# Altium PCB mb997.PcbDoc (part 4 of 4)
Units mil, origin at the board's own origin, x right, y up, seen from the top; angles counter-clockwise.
Board outline 2598.43 x 3818.9 mil, 2 copper layers (Top, Bottom), stack 62.402 mil thick; 205 components, 190 nets, 761 pads, 492 vias.
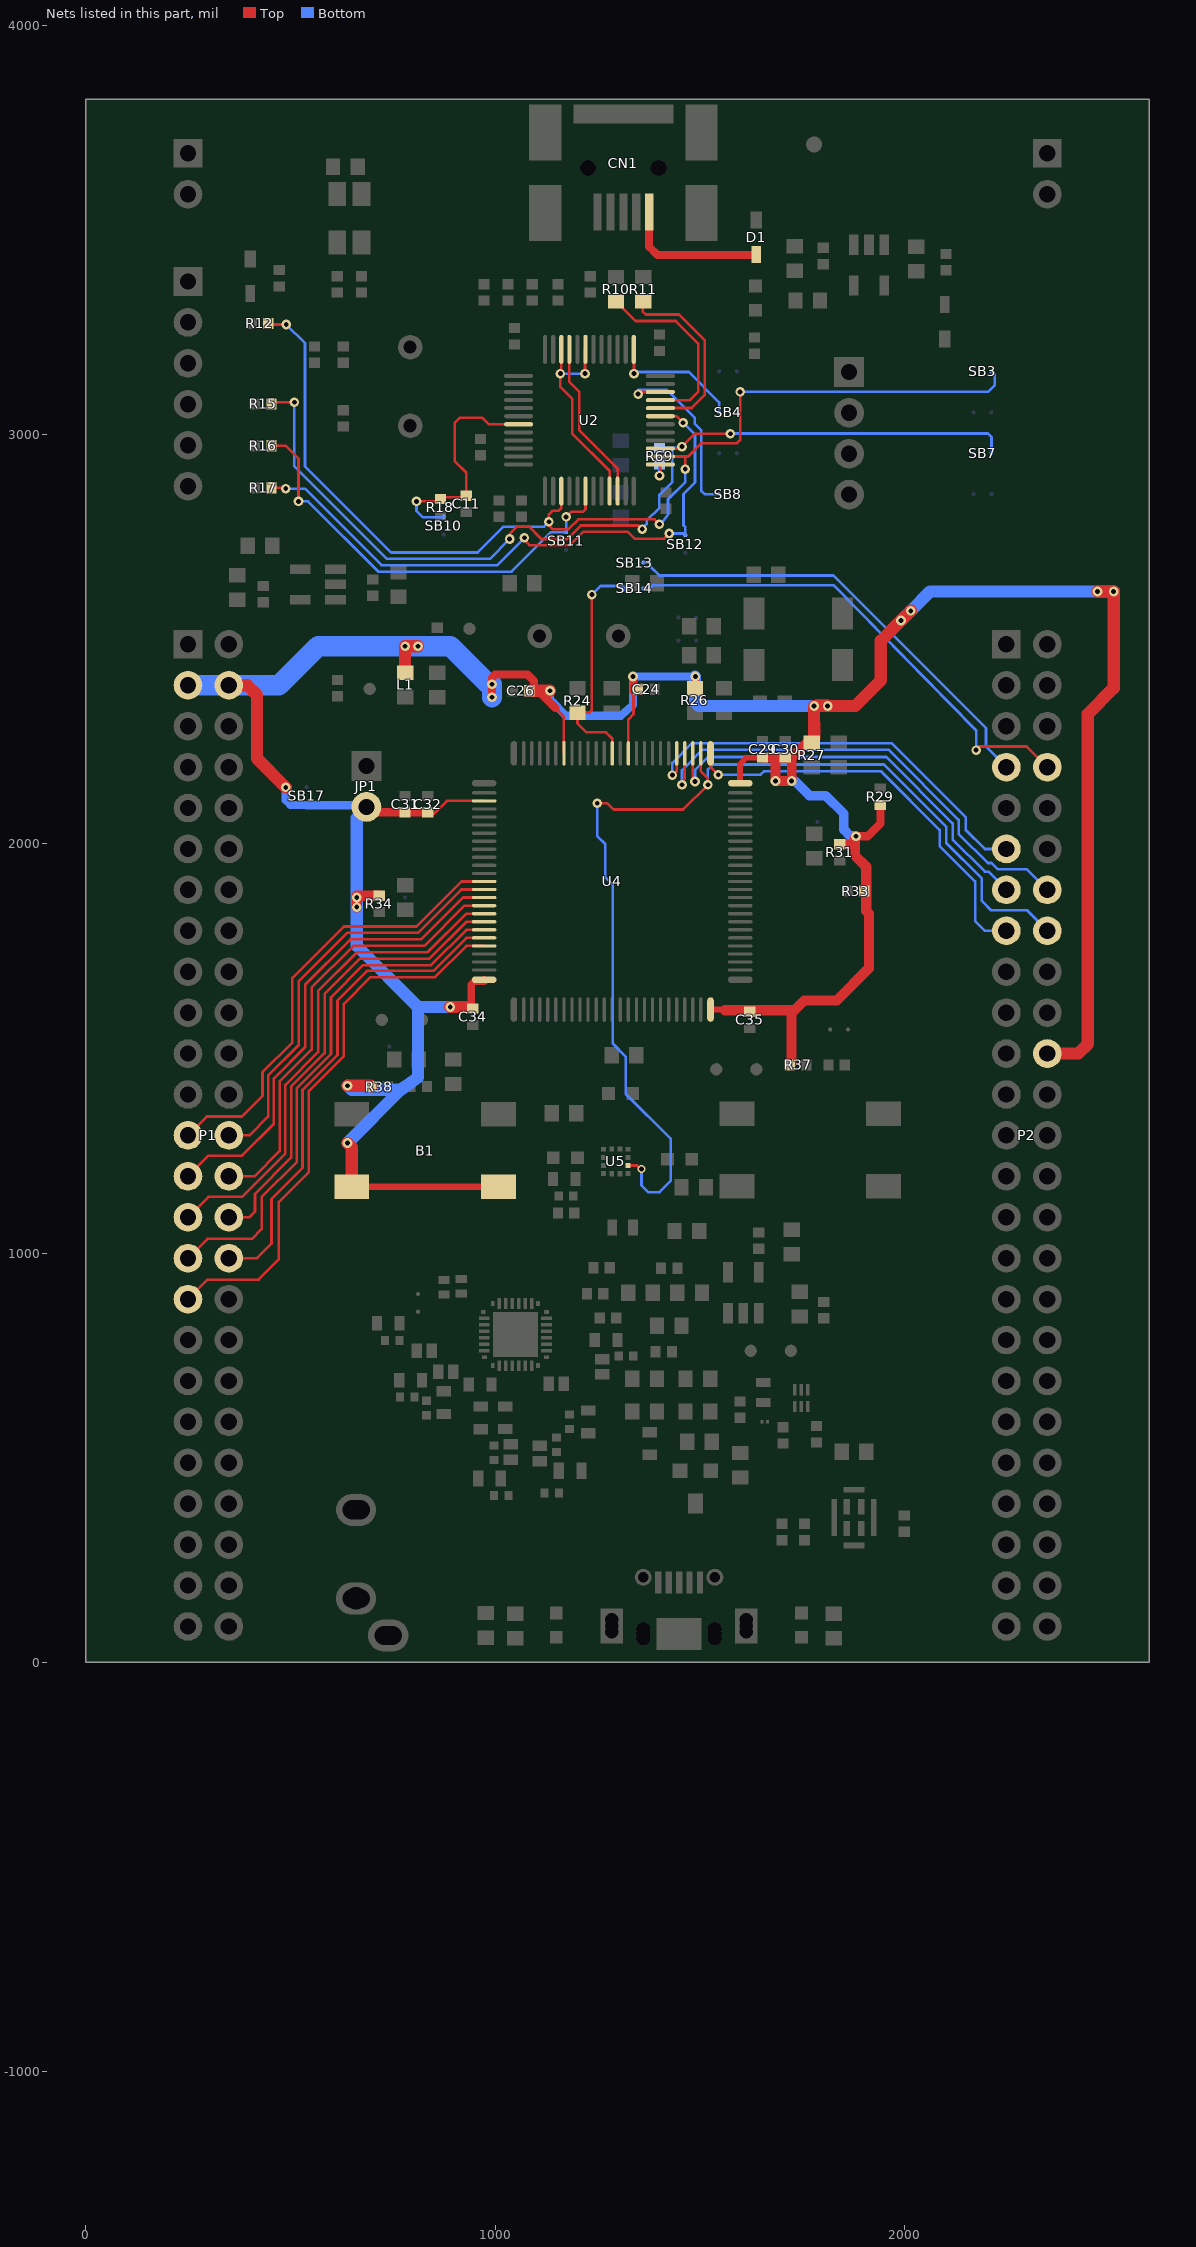
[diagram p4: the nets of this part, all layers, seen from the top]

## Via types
v1: diameter 23.62, hole 11.81, Top to Bottom, 485 vias
v2: diameter 19.68, hole 11.81, Top to Bottom, 7 vias

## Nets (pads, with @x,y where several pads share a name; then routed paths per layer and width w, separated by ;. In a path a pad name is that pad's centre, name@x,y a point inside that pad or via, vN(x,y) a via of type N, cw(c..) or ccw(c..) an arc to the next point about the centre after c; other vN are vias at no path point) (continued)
PE2: P2.15 U4.1 | length 1009.2
  Top w6.5: U4.1@1526.12,2220.94 1526.12,2186.9 1527.21,2186.9 v1(1545.21,2168.9)
  Bottom w6.5: v1(1545.21,2168.9) 1648.53,2168.9 1656.53,2176.9 1943.36,2176.9 2086.21,2034.05 2086.21,1994.7 2172.78,1908.13 2172.78,1811.01 2196.39,1787.4 P2.15@2249.21,1787.4
PE3: P2.16 U4.2 U5.2 | length 2644.3
  Top w6.5: v1(1249.21,2098.9) 1274.18,2098.9 1289.21,2083.87 1459.21,2083.87 v1(1519.57,2144.23) 1519.57,2159.97 1502.5,2177.04 U4.2@1502.5,2220.94 ; U5.2@1324.72,1214.06 1346.92,1214.06 1355.77,1205.2 v2(1357.32,1205.2)
  Bottom w6.5: v1(1249.21,2098.9) 1249.21,2018.9 1269.21,1998.9 1269.21,1917.32 1287.24,1899.29 1287.24,1511.65 1318.9,1480 1318.9,1389.21 1429.21,1278.9 1429.21,1176.69 1401.42,1148.9 1373.63,1148.9 1357.32,1165.22 v2(1357.32,1205.2) ; v1(1519.57,2144.23) 1519.57,2181.44 1532.03,2193.9 1949.97,2193.9 2101.95,2041.92 2101.95,2002.57 2188.52,1916 2188.52,1860.91 2211.83,1837.6 2299.01,1837.6 P2.16@2349.21,1787.4
PE4: P2.13 U4.3 | length 1034.1
  Top w6.5: U4.3@1482.81,2220.94 1482.81,2152.1 v1(1488.09,2152.1)
  Bottom w6.5: v1(1488.09,2152.1) 1488.09,2180.43 1519.56,2211.9 1955.58,2211.9 2117.69,2049.79 2117.69,2010.44 2196.39,1931.74 2204.88,1931.74 P2.13@2249.21,1887.4
PE5: P2.14 U4.4 | length 1190.1
  Top w6.5: v1(1456.61,2144.23) 1456.61,2153.45 1463.13,2159.97 U4.4@1463.13,2220.94
  Bottom w6.5: v1(1456.61,2144.23) 1456.61,2179.67 1506.84,2229.9 1961.19,2229.9 2132.58,2058.51 2132.58,2024.48 2203.84,1953.23 2212.56,1953.23 2227.87,1937.91 2298.7,1937.91 P2.14@2349.21,1887.4
PE6: P2.11 U4.5 | length 1050.3
  Top w6.5: v1(1433,2167.84) 1440.87,2175.71 1443.44,2175.71 U4.5@1443.44,2220.94
  Bottom w6.5: v1(1433,2167.84) 1433,2197.9 1481,2245.9 1968.8,2245.9 2149.46,2065.24 2149.46,2034.33 2196.39,1987.4 P2.11@2249.21,1987.4
PE7: P1.25 U4.38 | length 1106.9
  Top w6.5: P1.25@249.21,1287.4 295.43,1333.62 381.21,1333.62 431.21,1383.62 431.21,1441.77 504.34,1514.9 504.34,1672.03 630.26,1797.95 807.52,1797.95 917.52,1907.95 U4.38@972.97,1907.95
PE8: P1.26 U4.39 | length 1022.5
  Top w6.5: P1.26@349.21,1287.4 399.21,1287.4 445.21,1333.4 445.21,1434.03 520.08,1508.9 520.08,1664.16 638.13,1782.21 811.27,1782.21 917.33,1888.26 U4.39@972.97,1888.26
PE9: P1.27 U4.40 | length 1160.4
  Top w6.5: P1.27@249.21,1187.4 299.72,1237.91 381.21,1237.91 459.21,1315.91 459.21,1426.29 535.82,1502.9 535.82,1656.29 646,1766.47 819.14,1766.47 921.25,1868.58 U4.40@972.97,1868.58
PE10: P1.28 U4.41 | length 1085.6
  Top w6.5: P1.28@349.21,1187.4 411.21,1187.4 473.21,1249.4 473.21,1418.55 551.56,1496.9 551.56,1648.42 653.87,1750.73 827.01,1750.73 925.18,1848.89 U4.41@972.97,1848.89
PE11: P1.29 U4.42 | length 1216.8
  Top w6.5: P1.29@249.21,1087.4 299.2,1137.39 381.21,1137.39 487.21,1243.39 487.21,1410.81 567.3,1490.9 567.3,1640.55 661.74,1734.99 835.1,1734.99 929.32,1829.21 U4.42@972.97,1829.21
PE12: P1.30 U4.43 | length 1134.6
  Top w6.5: P1.30@349.21,1087.4 399.21,1087.4 413.02,1101.21 413.02,1144.7 501.21,1232.9 501.21,1406.9 583.04,1488.73 583.04,1632.68 669.61,1719.25 839.05,1719.25 929.32,1809.52 U4.43@972.97,1809.52
PE13: P1.31 U4.44 | length 1288.5
  Top w6.5: P1.31@249.21,987.4 296.37,1034.56 405.21,1034.56 429.21,1058.56 429.21,1136.9 515.21,1222.9 515.21,1402.9 598.78,1486.47 598.78,1624.81 677.48,1703.51 842.99,1703.51 929.32,1789.84 U4.44@972.97,1789.84
PE14: P1.32 U4.45 | length 1201.5
  Top w6.5: P1.32@349.21,987.4 417.77,987.4 453.24,1022.87 453.24,1131.9 529.21,1207.87 529.21,1398.9 614.52,1484.21 614.52,1616.94 687.2,1689.61 848.78,1689.61 929.32,1770.15 U4.45@972.97,1770.15
PE15: P1.33 U4.46 | length 1353.7
  Top w6.5: P1.33@249.21,887.4 296.89,935.08 421.39,935.08 471.21,984.9 471.21,1124.9 544.71,1198.4 544.71,1396.4 630.26,1481.95 630.26,1609.07 695.27,1674.08 853.19,1674.08 929.58,1750.47 U4.46@972.97,1750.47
PH0: P2.7 SB13.2 | length 1126.1
  Bottom w6.5: SB13.2@1362.18,2687.26 1378.81,2687.26 1378.81,2678.18 1401.21,2655.78 1826.5,2655.78 2199.21,2283.07 2199.21,2237.4 P2.7@2249.21,2187.4
PH1: P2.8 SB14.2 | length 1214
  Top w6.5: v1(2175.21,2228.9) 2181.21,2234.9 2181.21,2237.91 2298.7,2237.91 P2.8@2349.21,2187.4
  Bottom w6.5: SB14.2@1362.18,2624.3 1377.97,2624.3 1385.84,2632.17 1826.5,2632.17 2175.21,2277.46 v1(2175.21,2228.9)
PH1-OSC_OUT: R24.2 SB14.1 U4.13 | length 588.8
  Top w6.5: v1(1236.21,2608.9) 1236.21,2326.9 1229.21,2319.9 R24.2@1201.21,2319.9 1201.21,2293.9 1222.84,2272.27 1270.59,2272.27 1285.96,2256.9 U4.13@1285.96,2220.94
  Bottom w6.5: v1(1236.21,2608.9) 1257.21,2629.9 1313.21,2629.9 1313.21,2618.63 ; 1311.84,2617.27 1313.21,2618.63 ; SB14.1@1318.88,2624.3 1313.21,2618.63
STM_JTCK: SB4.2 U2.37 | length 324.4
  Top w6.5: U2.37@1338.61,3208.23 1338.61,3198.9 1339.21,3198.29 v1(1339.21,3148.9)
  Bottom w6.5: v1(1339.21,3148.9) 1343.21,3152.89 1473.21,3152.89 1547.2,3078.9 SB4.2@1547.2,3054.37
STM_JTMS: SB8.2 U2.34 | length 468.1
  Top w6.5: v1(1349.21,3098.9) 1349.21,3103.59 1348.91,3103.9 U2.34@1403.57,3103.9
  Bottom w6.5: v1(1349.21,3098.9) 1349.21,3108.9 1419.21,3108.9 1487.96,3040.15 1487.96,3026.02 1503.83,3010.15 1503.83,2862.24 1511.7,2854.37 SB8.2@1547.2,2854.37
STM_RST: C11.2 R18.1 SB10.2 U2.7 | length 580.6
  Top w6.5: v1(807.81,2836.7) 856.53,2836.7 R18.1@866.14,2842.83 870.03,2846.73 925.15,2846.73 C11.2@929.13,2850.71 929.21,2906.9 901.41,2934.7 901.41,3029.24 913.58,3041.41 968.16,3041.41 984.41,3025.16 U2.7@1057.11,3025.16
  Bottom w6.5: v1(807.81,2836.7) 807.81,2813.3 823.41,2797.7 870.21,2797.7 871.73,2799.21 SB10.2@874.02,2799.21
SWIM: U2.22 U2.45 | length 395.4
  Top w6.5: U2.45@1181.13,3208.23 1181.13,3128.92 1205.23,3104.82 1205.23,3011.33 1299.24,2917.32 U2.22@1299.24,2861.77
SWIM_IN: U2.21 U2.43 U2.46 | length 517.1
  Top w6.5: U2.46@1161.44,3208.23 1161.44,3153.54 1159.21,3151.32 v1(1159.21,3148.9) 1159.21,3116.4 1188.01,3087.6 1188.01,3003.14 1279.55,2911.6 U2.21@1279.55,2861.77 ; v1(1219.21,3148.9) 1219.21,3206.94 U2.43@1220.5,3208.23
  Bottom w6.5: v1(1159.21,3148.9) v1(1219.21,3148.9)
T_JTCK: R12.2 SB3.1 U2.15 U2.26 | length 2706.2
  Top w6.5: R12.2@445.2,3271.65 447.95,3268.9 v1(489.21,3268.9) ; U2.15@1161.44,2861.77 1161.44,2821.1 1154.17,2813.82 1140.14,2813.82 1131.21,2804.9 v1(1131.21,2786.9) 1131.21,2777.9 1140.21,2768.9 1179.21,2768.9 1203.21,2792.9 1389.21,2792.9 v1(1401.21,2780.9) ; U2.26@1403.57,2946.42 1464.48,2946.42 ; v1(1464.48,2915.49) 1464.48,2946.42 ; v1(1598.43,3104.37) 1598.43,2986.4 1590.93,2978.9 1504.19,2978.9 1471.71,2946.42 1464.48,2946.42
  Bottom w6.5: v1(489.21,3268.9) 535.31,3223.3 535.31,2922 745.41,2711.9 957.21,2711.9 1020.21,2774.9 1119.21,2774.9 v1(1131.21,2786.9) ; v1(1401.21,2780.9) 1404.38,2780.9 1422.38,2804.9 1422.38,2841.91 1464.48,2884.01 v1(1464.48,2915.49) ; v1(1598.43,3104.37) 2204.72,3104.37 2220.47,3120.12 2220.47,3146.46 SB3.1@2212.56,3154.37
T_JTMS: R15.2 R69.2 SB7.1 U2.27 | length 2380.6
  Top w6.5: R15.2@453.07,3074.8 457.17,3078.9 v1(509.21,3078.9) ; v1(1035.21,2744.9) 1035.21,2756.9 1053.21,2774.9 1082.49,2774.9 1112.49,2744.9 1176.21,2744.9 1209.21,2777.9 1350.21,2777.9 v1(1359.21,2768.9) ; U2.27@1403.57,2966.1 1448.74,2966.1 v1(1456.61,2970.58) 1488.09,3002.06 v1(1574.66,3002.06)
  Bottom w6.5: v1(509.21,3078.9) 509.21,2922.5 735.41,2696.3 987.21,2696.3 1035.21,2744.3 v1(1035.21,2744.9) ; v1(1359.21,2768.9) 1359.21,2770.07 1370.04,2780.9 1370.04,2789.57 1401.13,2820.66 1401.13,2852.14 1433,2884.01 1433,2966.97 ; R69.2@1401.52,2966.97 1433,2966.97 ; v1(1456.61,2970.58) 1456.61,2968.77 1454.81,2966.97 1433,2966.97 ; v1(1574.66,3002.06) 1575.09,3002.48 2204.26,3002.48 2212.56,2994.19 SB7.1@2212.56,2954.37
T_NRST: R16.2 SB11.1 U2.18 | length 1085.7
  Top w6.5: R16.2@453.07,2972.44 488.19,2972.44 519.21,2941.42 v1(519.21,2836.7) ; v1(1173.21,2798.9) 1185.57,2811.26 1214.85,2811.26 1220.5,2816.9 U2.18@1220.5,2861.77
  Bottom w6.5: v1(519.21,2836.7) 542.61,2836.7 714.21,2665.1 1040.21,2665.1 1136.7,2761.58 SB11.1@1173.21,2761.58 v1(1173.21,2798.9)
T_SWDIO_IN: R69.1 U2.25 | length 56.2
  Top w6.5: v1(1401.52,2899.75) 1403.57,2899.75 U2.25@1403.57,2926.73
  Bottom w6.5: v1(1401.52,2899.75) R69.1@1401.52,2926.97
T_SWO: R17.2 SB12.1 U2.31 | length 1519.3
  Top w6.5: R17.2@453.07,2870.08 485.83,2870.08 v1(488.01,2867.9) ; v1(1071.21,2747.9) 1071.21,2741.9 1083.21,2729.9 1182.21,2729.9 1215.21,2762.9 1323.21,2762.9 1340.58,2745.53 1412.58,2745.53 v1(1425.13,2758.09) ; U2.31@1403.57,3044.84 1443.27,3044.84 v1(1459.21,3028.9)
  Bottom w6.5: v1(488.01,2867.9) 534.81,2867.9 722.01,2680.7 1005.21,2680.7 1071.21,2746.7 v1(1071.21,2747.9) ; v1(1425.13,2758.09) 1460.56,2758.09 SB12.1@1464.48,2754.16 1464.48,2773.83 1460.23,2778.08 1460.23,2854.85 1488.09,2882.71 1488.09,3000.02 v1(1459.21,3028.9)
U5V: CN1.1 D1.1 | length 354.8
  Top w19.68: CN1.1@1376.23,3543.35 1376.23,3458.9 1396.23,3438.9 1636.46,3438.9 D1.1@1637.76,3440.2
USB_DM: R11.2 U2.32 | length 462.5
  Top w6.5: R11.2@1362.17,3325.16 1360.21,3325.16 1360.21,3301.12 1368.08,3293.25 1449.12,3293.25 1511.7,3230.66 1511.7,3096.5 1480.22,3065.02 1403.57,3065.02 U2.32@1403.57,3064.53
USB_DP: R10.2 U2.33 | length 462.1
  Top w6.5: R10.2@1295.24,3325.16 1342.89,3277.51 1440.87,3277.51 1495.96,3222.42 1495.96,3104.37 1475.81,3084.21 U2.33@1403.57,3084.21
VDD: B1.3 B1.4 C24.1 C26.2 C29.2 C30.2 C31.2 C32.2 C34.2 C35.1 JP1.2 L1.1 P1.3 P1.4 P2.22 R26.1 R27.2 R29.1 R31.2 R33.1 R34.1 R37.2 R38.2 SB17.2 U4.11 U4.19 U4.28 U4.50 U4.75 U4.100 | length 9415.6
  Top w6.5: C32.2@834.88,2077.01 838.49,2073.4 850.7,2073.4 882.1,2104.8 U4.28@972.97,2104.8 ; 1102.36,2374.02 1104.86,2374.02 ; 1146.81,2332.06 1167.85,2311.02 U4.19@1167.85,2220.94 ; U4.11@1325.33,2220.94 1325.33,2303.9 1338.11,2316.68 C24.1@1338.11,2372.4 ; 1685.04,2208.66 1685.04,2210.16 ; 1879.42,1971.09 1880.51,1970 ; R33.1@1901.59,1884.52 1901.59,1918.01 1906.43,1922.85
  Top w13.78: U4.100@1598.96,2148.11 1598.96,2151.41 1598.27,2152.1 1598.27,2194.75 1614.01,2210.49 1636.76,2210.49 C29.2@1653.36,2210.8
  Top w15: U4.75@1526.12,1594.96 1559.75,1594.96 1561.71,1592.99
  Top w15.75: B1.3@649.62,1161.92 B1.4@1007.89,1161.92
  Top w18: C34.2@937.19,1601.2 940.8,1597.59 C34.2@941.87,1596.52 ; C34.2@945.06,1597.59 C34.2@941.87,1596.52 ; U4.50@972.97,1667.79 972.97,1664.16 949.74,1664.16 941.87,1656.29 C34.2@941.87,1596.52
  Top w19.68: v1(992.13,2358.27) v1(992.13,2389.76) 992.13,2405.51 1000,2413.39 1078.74,2413.39 1094.49,2397.64 C26.2@1094.49,2374.02 ; v1(1336.71,2408.9) 1337.37,2408.16 1338.11,2407.42 1338.11,2372.4 1339.05,2371.46 1340.53,2372.4 C24.1@1349.21,2377.9 ; R26.1@1488.19,2380.39 1488.19,2407.87 v1(1489.21,2408.9)
  Top w20: JP1.2@693.22,2094.23 710.44,2077.01 C31.2@779.79,2077.01 C32.2@834.88,2077.01 ; 1104.86,2374.02 1119.36,2359.52 1146.81,2332.06 ; v1(1881.59,2018.31) 1909.73,2018.31 1941.21,2049.79 R29.1@1941.21,2094.9
  Top w23.62: C29.2@1653.36,2210.8 1685.04,2210.16 C30.2@1708.45,2210.8 1724.41,2210.16 ; v1(1685.04,2153.54) v1(1724.41,2153.54) 1724.41,2210.16 ; R27.2@1773.21,2246.9 1773.14,2246.26 1760.51,2246.26 1724.41,2210.16 ; R31.2@1842.24,1998.96 1875.16,1998.96 v1@1879.42,2018.31 ; 1879.42,1971.09 v1@1879.42,2018.31 ; v1(1881.59,2018.31) v1@1879.42,2018.31
  Top w25: v1(661.74,1845.17) v1(661.74,1868.78) 661.74,1873.04 R34.1@716.83,1873.04 ; 1561.71,1592.99 1637.8,1592.99 ; C35.1@1621.88,1589.72 1637.8,1592.99 ; v1(1685.04,2153.54) 1685.04,2208.66 ; R37.2@1719.93,1459.54 1724.05,1463.65 1724.05,1483.16 1723.95,1522.5 1723.95,1585.46 ; 1880.51,1970 1906.43,1944.07 1906.43,1922.85 1906.43,1836.07 1913.07,1829.43 1913.07,1695.64 1834.37,1616.94 1755.43,1616.94 1723.95,1585.46 ; 1637.8,1592.99 1723.95,1592.99 1723.95,1585.46
  Top w30: P1.4@349.21,2387.4 394.16,2387.4 417.77,2363.79 417.77,2208.21 v1(488.19,2137.8) ; v1(639.21,1268.9) 649.62,1258.49 B1.3@649.62,1161.92 ; v1(639.21,1408.9) 695.21,1408.9 R38.2@697.21,1406.9 ; L1.1@779.79,2418.2 v1(779.79,2482.64) v1(811.27,2482.64) ; v1(889.97,1601.2) C34.2@937.19,1601.2 ; C26.2@1082.99,2374.02 1094.49,2374.02 1102.36,2374.02 ; 1104.86,2374.02 v1(1133.86,2374.02) ; R27.2@1773.21,2246.9 1773.67,2253.12 1779.53,2258.98 v1(1779.21,2336.9) 1785.2,2336.66 1879.59,2336.66 1942.04,2399.11 1942.04,2495.86 v1(1991.77,2545.6) v1(2015.38,2569.21) ; P2.22@2349.21,1487.4 2424.62,1487.4 2448.23,1511.01 2448.23,2317.37 2511.19,2380.33 v1(2511.19,2616.43) v1(2471.84,2616.43)
  Bottom w6.5: v1@1133.86,2372.46 v1(1133.86,2374.02)
  Bottom w19.68: v1(488.19,2137.8) 488.19,2106.3 499.21,2095.28 SB17.2@539.21,2095.28 540.26,2094.23 JP1.2@693.22,2094.23 ; v1@1133.86,2372.46 1133.86,2352.33 1173.29,2312.9 1307.08,2312.9 1334.1,2336.51 ; v1(1336.71,2408.9) 1488.09,2408.9 v1(1489.21,2408.9)
  Bottom w20: 1334.1,2336.51 1336.71,2339.13 v1(1336.71,2408.9)
  Bottom w23.62: 1708.66,2153.54 v1(1724.41,2153.54) 1732.06,2153.54 1768.08,2117.53 1807.67,2117.53 1851.8,2073.4 1851.8,2034.64 1867.54,2018.9 1878.5,2018.9 v1(1881.59,2018.31)
  Bottom w25: v1(1685.04,2153.54) 1708.66,2153.54
  Bottom w30: v1(639.21,1268.9) 769.21,1398.9 ; v1(639.21,1408.9) 649.21,1398.9 769.21,1398.9 ; JP1.2@693.22,2094.23 661.74,2062.75 v1(661.74,1868.78) v1(661.74,1845.17) 661.74,1750.73 811.27,1601.2 ; v1(889.97,1601.2) 811.27,1601.2 ; v1@1488.09,2408.9 1488.09,2346.02 1497.21,2336.9 1503.21,2336.96 v1@1779.52,2336.96 ; v1(1779.21,2336.9) v1@1779.52,2336.96 ; v1(1812.21,2336.9) 1812.15,2336.96 1811.06,2338.05 v1@1784.99,2338.05 ; v1(1991.77,2545.6) v1(2015.38,2569.21) 2062.6,2616.43 v1(2471.84,2616.43) v1(2511.19,2616.43) ; 769.21,1398.9 811.27,1428.9 811.27,1601.2 ; v1@1779.52,2336.96 1783.9,2336.96 v1@1784.99,2338.05 ; v1@1779.52,2336.96 v1@1784.99,2338.05
  Bottom w50: P1.3@249.21,2387.4 P1.4@349.21,2387.4 471.69,2387.4 566.93,2482.64 v1(779.79,2482.64) v1(811.27,2482.64) 890.76,2482.64 983.63,2389.76 v1(992.13,2389.76) v1(992.13,2358.27)
pads on no net: CN1.6 CN1.7 CN1.8 CN1.9 CN1.10 CN1.11 CN1.12 CN5.0/3 CN5.0/4 CN5.0/5 CN5.6 CN5.6/2 CN5.6/3 CN5.6/4 CN5.6/5 CN5.6/6 P1.48 U2.4 U2.11 U2.12 U2.13 U2.14 U2.16 U2.17 U2.19 U2.28 U2.38 U2.39 U2.40 U2.41 U2.42 U5.5 U7.16 U7.17 U7.18 U7.20 U7.31 X3.2 X3.3

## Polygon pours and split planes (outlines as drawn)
GND on Top "Top-GND" (hatched 45Degree grid 11.81 track 13.78, remove dead copper, pour order 2): 6.89,3785.24 2591.54,3785.24 2591.54,6.89 6.89,6.89
GND on Bottom "Bottom-GND" (hatched 45Degree grid 11.81 track 13.78, remove dead copper, pour order 0): 6.89,3793.11 2591.54,3793.11 2591.54,6.89 6.89,6.89

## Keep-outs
Top:
  region: 1516,118 1577,118 1577,77 1516,77
Bottom:
  circle w7.87: c1779.41,3709.21 r29.33
Keep-Out Layer:
  the board outline again, w10

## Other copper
Top:
  pour cut-out: 1799.96,802.33 1677.96,802.33 1677.96,709.33 1799.96,709.33
  pour cut-out: 1706.76,1495.68 1584.76,1495.68 1584.76,1402.68 1706.76,1402.68
  pour cut-out: 791.47,1616.5 669.47,1616.5 669.47,1523.5 791.47,1523.5
  pour cut-out: 983.79,2456.83 983.79,2578.83 890.79,2578.83 890.79,2456.83
  pour cut-out: 740,2408 740,2530 647,2530 647,2408
  text "TOP Layer" at -33,-1009.78 h118.11
  text ".GTL" at 1643,-1016.77 h118.11
Bottom:
  pour cut-out: 1747.93,2033.42 1824.93,2033.42 1824.93,2103.42 1747.93,2103.42
  pour cut-out: 741,1888 818,1888 818,1958 741,1958
  text "Bottom Layer" at 2736.5,-997.78 h118.11
  text ".GBL" at 1054,-1010.77 h118.11

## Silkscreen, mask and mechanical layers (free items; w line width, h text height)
Silkscreen Top:
  circle w12: c2165.35,2555.12 r15.75
  circle w12: c165.35,3374.02 r17.61
  circle w12: c2165.35,2555.12 r7.87
  circle w12: c157.48,2547.24 r7.87
  circle w12: c1850.39,3232.28 r7.87
  circle w12: c2165.35,2555.12 r17.61
  circle w12: c1850.39,3232.28 r15.75
  circle w12: c165.35,3374.02 r15.75
  circle w12: c1850.39,3232.28 r7.87
  circle w12: c157.48,2547.24 r15.75
  circle w12: c165.35,3374.02 r7.87
  circle w12: c157.48,2547.24 r7.87
  circle w12: c2165.35,2555.12 r7.87
  circle w12: c157.48,2547.24 r17.61
  circle w12: c1850.39,3232.28 r17.61
  circle w12: c165.35,3374.02 r7.87
  lines w5: 442.52,3435.72 462.97,3435.72 ; 678.87,2305.89 707,2305.89 ; 692.94,2295.66 692.94,2316.11 ; 883.35,1569.44 903.81,1569.44 ; 893.58,1555.37 893.58,1583.5 ; 922.66,2354.72 950.78,2354.72 ; 936.72,2344.49 936.72,2364.94 ; 1143.7,605.92 1171.82,605.92 ; 1157.76,595.69 1157.76,616.14 ; 1457.32,1449.18 1477.77,1449.18 ; 1467.55,1435.12 1467.55,1463.24 ; 1529.34,727.91 1549.79,727.91 ; 1539.57,713.85 1539.57,741.97 ; 1678.7,3531.03 1699.15,3531.03 ; 2036.98,3226.53 2057.44,3226.53
  lines w6: 330.71,2704.72 342.52,2692.91 417.32,2692.91 431.1,2679.13 431.1,2673.23 ; 803.15,2578.74 858.27,2578.74 874.02,2594.49 ; 897.84,3419.17 897.84,3379.82 937.19,3379.82 ; 968.67,1388.71 976.54,1380.84 1047.37,1380.84 1070.98,1404.45 ; 1430.55,502.5 1430.55,612.5 ; 1440.87,2466.9 1433,2474.77 1433,2561.34 1472.35,2600.69 ; 1629.75,704.86 1635.74,710.84 1764.13,710.84
  lines w10: 0,0 2598.42,0 2598.42,3818.9 0,3818.9 0,0
  lines w19.68: 1754.92,2833.66 1792.42,2833.66 1792.42,2968.66 1754.92,2968.66 1754.92,2833.66 ; 1754.92,3059.41 1792.42,3059.41 1792.42,3194.41 1754.92,3194.41 1754.92,3059.41
  lines w39.37: 1942.42,2845.1 1964.92,2845.1 1964.92,2965.1 1942.42,2965.1 1942.42,2845.1 ; 1942.42,3070.47 1964.92,3070.47 1964.92,3190.47 1942.42,3190.47 1942.42,3070.47
  text "STM32F407G-DISC1" at 340,3706 h110.24
  text "COM" at 736.18,3496.89 h55
  text "MB997G" at 2199.21,3260.36 h118.11
  text "PWR" at 1549.21,3248.9 h78.74 r90
  text "SWD" at 165.35,3082.68 h118.11 r90
  text "ST-LINK" at 1719.21,2878.9 h98.43 r90
  text "DISCOVERY" at 2061,2835 h98.43 r90
  text "J" at 2145.63,2835.31 h600
  text "www.st.com/stm32f4-discovery" at 670.17,2703.33 h118.11
  text "GND" at 39.37,2468.9 h78.74
  text "GND" at 413.39,2468.9 h78.74
  text "GND" at 2047.24,2468.9 h78.74
  text "GND" at 2421.26,2468.9 h78.74
  text "VDD" at 39.37,2368.9 h78.74
  text "VDD" at 413.39,2368.9 h78.74
  text "5V" at 2047.24,2368.9 h78.74
  text "5V" at 2421.26,2368.9 h78.74
  text "GND" at 39.37,2268.9 h78.74
  text "NRST" at 413.39,2268.9 h78.74
  text "3V" at 2047.24,2268.9 h78.74
  text "3V" at 2421.26,2268.9 h78.74
  text "PC1" at 39.37,2168.9 h78.74
  text "PC0" at 413.39,2168.9 h78.74
  text "PH0" at 2047.24,2168.9 h78.74
  text "PH1" at 2421.26,2168.9 h78.74
  text "PC3" at 39.37,2068.9 h78.74
  text "PC2" at 413.39,2068.9 h78.74
  text "PC14" at 2047.24,2068.9 h78.74
  text "PC15" at 2421.26,2068.9 h78.74
  text "Idd" at 637.8,1972.44 h78.74
  text "PA1" at 39.37,1968.9 h78.74
  text "PA0" at 413.39,1968.9 h78.74
  text "PE6" at 2047.24,1968.9 h78.74
  text "PC13" at 2421.26,1968.9 h78.74
  text "PA3" at 39.37,1868.9 h78.74
  text "PA2" at 413.39,1868.9 h78.74
  text "PE4" at 2047.24,1868.9 h78.74
  text "PE5" at 2421.26,1868.9 h78.74
  text "PA5" at 39.37,1768.9 h78.74
  text "PA4" at 413.39,1768.9 h78.74
  text "PE2" at 2047.24,1768.9 h78.74
  text "PE3" at 2421.26,1768.9 h78.74
  text "PA7" at 39.37,1668.9 h78.74
  text "PA6" at 413.39,1668.9 h78.74
  text "PE0" at 2047.24,1668.9 h78.74
  text "PE1" at 2421.26,1668.9 h78.74
  text "PC5" at 39.37,1568.9 h78.74
  text "PC4" at 413.39,1568.9 h78.74
  text "PB8" at 2047.24,1568.9 h78.74
  text "PB9" at 2421.26,1568.9 h78.74
  text "PB1" at 39.37,1468.9 h78.74
  text "PB0" at 413.39,1468.9 h78.74
  text "BOOT0" at 2007.87,1468.9 h78.74
  text "VDD" at 2421.26,1468.9 h78.74
  text "GND" at 39.37,1368.9 h78.74
  text "PB2" at 413.39,1368.9 h78.74
  text "PB6" at 2047.24,1368.9 h78.74
  text "PB7" at 2421.26,1368.9 h78.74
  text "PE7" at 39.37,1268.9 h78.74
  text "PE8" at 413.39,1268.9 h78.74
  text "PB4" at 2047.24,1268.9 h78.74
  text "PB5" at 2421.26,1268.9 h78.74
  text "PE9" at 39.37,1168.9 h78.74
  text "PE10" at 413.39,1168.9 h78.74
  text "PD7" at 2047.24,1168.9 h78.74
  text "PB3" at 2421.26,1168.9 h78.74
  text "Reset" at 1793.83,1070.56 h78.74
  text "PE11" at 39.37,1068.9 h78.74
  text "PE12" at 413.39,1068.9 h78.74
  text "User" at 746.21,1068.9 h78.74
  text "PD5" at 2047.24,1068.9 h78.74
  text "PD6" at 2421.26,1068.9 h78.74
  text "PE13" at 39.37,968.9 h78.74
  text "PE14" at 413.39,968.9 h78.74
  text "PD3" at 2047.24,968.9 h78.74
  text "PD4" at 2421.26,968.9 h78.74
  text "PE15" at 39.37,868.9 h78.74
  text "PB10" at 413.39,868.9 h78.74
  text "PD1" at 2047.24,868.9 h78.74
  text "PD2" at 2421.26,868.9 h78.74
  text "PB12" at 413.39,768.9 h78.74
  text "PC12" at 2047.24,768.9 h78.74
  text "PD0" at 2421.26,768.9 h78.74
  text "PB11" at 39.37,767.72 h78.74
  text "PB14" at 413.39,668.9 h78.74
  text "PC10" at 2047.24,668.9 h78.74
  text "PC11" at 2421.26,668.9 h78.74
  text "PB13" at 39.37,665.35 h78.74
  text "PB15" at 39.37,568.9 h78.74
  text "PD8" at 413.39,568.9 h78.74
  text "PA14" at 2047.24,568.9 h78.74
  text "PA15" at 2421.26,568.9 h78.74
  text "PD9" at 39.37,468.9 h78.74
  text "PD10" at 413.39,468.9 h78.74
  text "PA10" at 2047.24,468.9 h78.74
  text "PA13" at 2421.26,468.9 h78.74
  text "PD12" at 413.39,368.9 h78.74
  text "PA8" at 2047.24,368.9 h78.74
  text "PA9" at 2421.26,368.9 h78.74
  text "PD11" at 39.37,366.14 h78.74
  text "PD14" at 413.39,268.9 h78.74
  text "PC8" at 2047.24,268.9 h78.74
  text "PC9" at 2421.26,268.9 h78.74
  text "PD13" at 39.37,263.78 h78.74
  text "PD15" at 39.37,168.9 h78.74
  text "NC" at 413.39,168.9 h78.74
  text "PC6" at 2047.24,168.9 h78.74
  text "PC7" at 2421.26,168.9 h78.74
  text "GND" at 39.37,68.9 h78.74
  text "GND" at 413.39,68.9 h78.74
  text "GND" at 2047.24,68.9 h78.74
  text "GND" at 2421.26,68.9 h78.74
  text "TOP Silksceen Overlay" at -33,-1009.78 h118.11
  text ".GTO" at 1613,-1018.46 h118.11
Silkscreen Bottom:
  lines w7.87: 1507.83,2772.99 1507.83,3192.99 1635.33,3192.99 1635.33,2772.99 1507.83,2772.99 ; 2129.88,2769.06 2129.88,3189.06 2257.38,3189.06 2257.38,2769.06 2129.88,2769.06
  text "DEFAULT" at 2049,2846 h98.43 r270
  text "RESERVED" at 1669,2835 h98.43 r270
  text "I" at 1461,671.9 h500
  text "C" at 1876.71,654.88 h400
  text "E" at 2142.75,642.38 h400
  text "G" at 791.51,636.43 h400
  text "F" at 1080.82,636.32 h400
  text "H" at 1565.03,313.46 h500
  text "Bottom silkscreen Overlay" at 2784,-1008.78 h118.11
  text ".GBO" at 1080,-1013.77 h118.11
Solder Mask Top:
  text "TOP Solder Mask" at -26,-1011.77 h118.11
  text ".GTS" at 1633,-1016.77 h118.11
Solder Mask Bottom:
  text "Bottom Solder Mask" at 2749.91,-998.77 h118.11
  text ".GBS" at 1042,-1006.77 h118.11
Layer_3:
  lines w6: 992.12,1223.9 1559.05,1223.9 ; 1319.21,924.69 1319.21,1491.62 ; 1155.21,1059.06 1155.21,1389.76 1482.21,1389.76 1482.21,1059.06 1155.21,1059.06
Board:
  the board outline again, w10
Drill Drawing:
  circle w10: c3326.36,446.88 r27.18
  circle w10: c3326.36,446.88 r45.31
  circle w10: c3326.36,243 r45.31
  lines w1: 0,1909.45 0.03,1909.45 ; 249.21,87.4 249.24,87.4 ; 249.21,2487.4 249.24,2487.4 ; 249.21,3587.4 249.24,3587.4 ; 249.21,3687.4 249.24,3687.4 ; 349.21,87.4 349.24,87.4 ; 1299.21,0 1299.24,0 ; 1299.21,3818.9 1299.24,3818.9 ; 2249.21,87.4 2249.24,87.4 ; 2349.21,87.4 2349.24,87.4 ; 2349.21,3687.4 2349.24,3687.4 ; 2598.43,1909.45 2598.45,1909.45
  lines w10: 3281.05,-187.4 3303.7,-187.4 3326.36,-210.06 3349.01,-187.4 3371.66,-187.4 3349.01,-164.75 3371.66,-142.1 3349.01,-142.1 3326.36,-119.45 3303.7,-142.1 3281.05,-142.1 3303.7,-164.75 3281.05,-187.4 ; 3281.05,84.43 3371.66,84.43 3326.36,-6.18 3281.05,84.43 ; 3281.05,605.45 3371.66,605.45 3371.66,696.06 3281.05,696.06 3281.05,605.45 ; 3281.05,809.32 3326.36,831.97 3371.66,809.32 3349.01,854.63 3371.66,899.93 3326.36,877.28 3281.05,899.93 3303.7,854.63 3281.05,809.32 ; 3281.05,1035.85 3303.7,1035.85 3303.7,1013.2 3349.01,1013.2 3349.01,1035.85 3371.66,1035.85 3371.66,1081.15 3349.01,1081.15 3349.01,1103.81 3303.7,1103.81 3303.7,1081.15 3281.05,1081.15 3281.05,1035.85 ; 3281.05,1262.38 3326.36,1217.07 3371.66,1262.38 3326.36,1307.68 3281.05,1262.38 ; 3281.05,1420.95 3281.05,1443.6 3303.7,1466.25 3281.05,1488.91 3281.05,1511.56 3303.7,1511.56 3326.36,1488.91 3349.01,1511.56 3371.66,1511.56 3371.66,1488.91 3349.01,1466.25 3371.66,1443.6 3371.66,1420.95 3349.01,1420.95 3326.36,1443.6 3303.7,1420.95 3281.05,1420.95 ; 3281.05,1624.82 3371.66,1624.82 3371.66,1715.43 3281.05,1715.43 3281.05,1624.82 ; 3299.17,1642.94 3353.54,1642.94 3353.54,1697.31 3299.17,1697.31 3299.17,1642.94
  lines w11.81: 3200.91,-271.22 5735.92,-271.22 ; 3200.91,1767.53 5735.92,1767.53 ; 3724.61,-475.09 3724.61,1971.41 ; 4278.09,-475.09 4278.09,1971.41 ; 5268.55,-475.09 5268.55,1971.41 ; 3200.91,-475.09 5735.92,-475.09 5735.92,1971.41 3200.91,1971.41 3200.91,-475.09
  lines w15: 3249.5,2845.45 3659.41,2845.45 4829.08,2845.45 5688.85,2845.45 6338.68,2845.45 ; 3249.5,2965.45 3659.41,2965.45 4829.08,2965.45 5688.85,2965.45 6338.68,2965.45 ; 3249.5,3085.45 3659.41,3085.45 4829.08,3085.45 5688.85,3085.45 6338.68,3085.45 ; 3249.5,3205.45 3659.41,3205.45 4829.08,3205.45 5688.85,3205.45 6338.68,3205.45 ; 3249.5,3325.45 3659.41,3325.45 4829.08,3325.45 5688.85,3325.45 6338.68,3325.45 ; 3249.5,3445.45 3659.41,3445.45 4829.08,3445.45 5688.85,3445.45 6338.68,3445.45 ; 3249.5,3565.45 6338.7,3565.45 ; 3659.41,3685.45 3659.41,2725.45 ; 4829.08,3685.45 4829.08,2725.45 ; 5688.85,3685.45 5688.85,2725.45 ; 3659.41,2725.45 3249.5,2725.45 3249.5,3685.45 6338.7,3685.45 6338.68,2725.45 ; 3659.41,2725.45 4829.08,2725.45 ; 4829.08,2725.45 5688.85,2725.45 ; 5688.85,2725.45 6338.68,2725.45 ; 6338.68,2725.45 6338.7,2725.45 ; 6338.68,2845.45 6338.7,2845.45 ; 6338.68,2965.45 6338.7,2965.45 ; 6338.68,3085.45 6338.7,3085.45 ; 6338.68,3205.45 6338.7,3205.45 ; 6338.68,3325.45 6338.7,3325.45 ; 6338.68,3445.45 6338.7,3445.45
  text "Layer" at 3309.5,3595.45 h60
  text "Name" at 3719.41,3595.45 h60
  text "Material" at 4889.08,3595.45 h60
  text "Thickness" at 5748.85,3595.45 h60
  text "1" at 3309.5,3475.45 h60
  text "Silkscreen Top" at 3719.41,3475.45 h60
  text "2" at 3309.5,3355.45 h60
  text "Solder Mask Top" at 3719.41,3355.45 h60
  text "Solder Resist" at 4889.08,3355.45 h60
  text "0.020mm" at 5748.85,3355.45 h60
  text "3" at 3309.5,3235.45 h60
  text "Top" at 3719.41,3235.45 h60
  text "Copper" at 4889.08,3235.45 h60
  text "0.018mm" at 5748.85,3235.45 h60
  text "4" at 3309.5,3115.45 h60
  text "Dielectric 1" at 3719.41,3115.45 h60
  text "FR-4" at 4889.08,3115.45 h60
  text "1.550mm" at 5748.85,3115.45 h60
  text "5" at 3309.5,2995.45 h60
  text "Bottom" at 3719.41,2995.45 h60
  text "Copper" at 4889.08,2995.45 h60
  text "0.018mm" at 5748.85,2995.45 h60
  text "6" at 3309.5,2875.45 h60
  text "Solder Mask Bottom" at 3719.41,2875.45 h60
  text "Solder Resist" at 4889.08,2875.45 h60
  text "0.020mm" at 5748.85,2875.45 h60
  text "7" at 3309.5,2755.45 h60
  text "Silkscreen Bottom" at 3719.41,2755.45 h60
  text "Symbol" at 3323.23,1828.7 h118.11
  text "Hit Count" at 3785.77,1828.7 h118.11
  text "Finished Hole Size" at 4339.26,1828.7 h118.11
  text "Plated" at 5329.71,1828.7 h118.11
  text "492" at 3785.77,1624.82 h98.43
  text "0.30mm" at 4339.26,1624.82 h98.43
  text "PTH" at 5329.71,1624.82 h98.43
  text "2" at 3785.77,1420.95 h98.43
  text "0.65mm" at 4339.26,1420.95 h98.43
  text "PTH" at 5329.71,1420.95 h98.43
  text "4" at 3785.77,1217.07 h98.43
  text "0.81mm" at 4339.26,1217.07 h98.43
  text "PTH" at 5329.71,1217.07 h98.43
  text "6" at 3785.77,1013.2 h98.43
  text "0.83mm" at 4339.26,1013.2 h98.43
  text "PTH" at 5329.71,1013.2 h98.43
  text "6" at 3785.77,809.32 h98.43
  text "0.90mm" at 4339.26,809.32 h98.43
  text "NPTH" at 5329.71,809.32 h98.43
  text "2" at 3785.77,605.45 h98.43
  text "1.00mm" at 4339.26,605.45 h98.43
  text "NPTH" at 5329.71,605.45 h98.43
  text "6" at 3785.77,401.57 h98.43
  text "1.00mm" at 4339.26,401.57 h98.43
  text "PTH" at 5329.71,401.57 h98.43
  text "110" at 3785.77,197.69 h98.43
  text "1.02mm" at 4339.26,197.69 h98.43
  text "PTH" at 5329.71,197.69 h98.43
  text "8" at 3785.77,-6.18 h98.43
  text "1.20mm" at 4339.26,-6.18 h98.43
  text "PTH" at 5329.71,-6.18 h98.43
  text "1" at 3785.77,-210.06 h98.43
  text "1.40mm" at 4339.26,-210.06 h98.43
  text "PTH" at 5329.71,-210.06 h98.43
  text "637 Total" at 3785.77,-413.93 h98.43
  text "Drill drawing" at -29,-1005.78 h118.11
  text ".GD1" at 1613,-1019.77 h118.11
TOP_TITLE_BOX:
  circle w10: c2992.16,-1279.66 r51.18
  region: 2973.47,-994.77 2362.16,-994.77 2334.83,-1064.66 2287.16,-1112.89 2232.16,-1039.66 2232.16,-974.66 2277.16,-919.66 2333.7,-904.77 2973.47,-904.77
  region: 2422.16,-1322.7 1998.7,-1322.7 2037.81,-1224.56 2347.16,-1224.56 2364.83,-1194.66 2451.78,-1294.99
  lines w10: 2037.81,-1224.56 2383.94,-1224.56 2263.23,-1085.27 cw(c2334.25,-1008.74) 2343.7,-904.77 3003.7,-904.77 2973.7,-994.77 ; 2168.27,-895.04 cw(c2263.79,-933.24) 2273.1,-830.79 ; 2169.81,-893.76 1998.7,-1322.7 2759.43,-1322.7 ccw(c2769.22,-1215.05) 2869.58,-1255.19 ; 2238.31,-1048.67 2451.78,-1294.99 ; 2248.31,-1048.67 2457.16,-1289.66 ; 2248.31,-1038.67 2457.16,-1279.66 ; 2252.16,-994.77 2763.7,-994.77 ; 2253.31,-1033.67 2462.16,-1274.66 ; 2258.31,-1028.67 2467.16,-1269.66 ; 2263.31,-1023.67 2472.16,-1264.66 ; 2268.31,-1018.67 2477.16,-1259.66 ; 2270.46,-941.8 2479.32,-1182.79 ; 2273.15,-830.8 3038.88,-830.8 2869.62,-1255.1 ; 2273.31,-1013.67 2480.02,-1252.19 ; 2273.31,-1003.67 2482.16,-1244.66 ; 2273.31,-993.67 2482.16,-1234.66 ; 2273.31,-958.67 2482.16,-1199.66 ; 2278.31,-988.67 2487.16,-1229.66 ; 2278.31,-973.67 2487.16,-1214.66 ; 2332.31,-1225.09 ccw(c2336.44,-1204.01) 2348.16,-1186.02 ; 2375.09,-994.24 ccw(c2374.06,-1016.58) 2361.06,-1034.77 2454.17,-1142.2 cw(c2383.15,-1218.73) 2411.99,-1319.07 ; 2622.38,-1314.66 2736.14,-984.77 ; 2631.14,-1312.7 2744.1,-985.11 ; 2636.14,-1312.7 2749.1,-985.11 ; 2646.14,-1312.7 2759.1,-985.11 ; 2656.14,-1312.7 2769.1,-985.11 ; 2666.14,-1312.7 2779.1,-985.11 ; 2676.14,-1312.7 2789.1,-985.11 ; 2686.14,-1312.7 2799.1,-985.11 ; 2696.14,-1312.7 2809.1,-985.11 ; 2706.14,-1312.7 2819.1,-985.11 ; 2714.35,-1314.66 2828.1,-984.77 ; 2828.1,-994.77 2973.47,-994.77 ; 2947.16,-994.66 2977.16,-904.66 ; 2953.7,-994.77 2983.7,-904.77 ; 2963.7,-994.77 2993.7,-904.77
  lines w11.81: -433.2,-1278.85 1929,-1278.85 ; -433.2,-1082 1929,-1082 ; -433.2,-885.15 1929,-885.15 ; 1141.6,-1475.7 1141.6,-885.15 ; 1929,-1475.7 1929,-688.3 ; 2622.38,-1314.66 2714.35,-1314.66 ; -433.19,-1475.7 -433.19,-688.3 3110.1,-688.3 3110.1,-1475.7 -433.2,-1475.7
  text "Project: '.Board_Name'" at -393.83,-814.91 h118.11
  text "Layer:" at -393.82,-1015.07 h118.11
  text "Gerber:" at 1180.54,-1015.07 h118.11
  text "Variant: '.VariantName'" at -393.83,-1211.92 h118.11
  text "Ref: '.Board_Reference'" at 1185.54,-1211.92 h118.11
  text "R" at 2972.16,-1309.66 h60
  text "Date: '.Board_Document_Date'" at -393.83,-1408.77 h118.11
  text "Rev: '.Board_PCB_Revision'" at 1183.29,-1408.77 h118.11
BOTTOM_TITLE_BOX:
  circle w10: c-284.49,-1273.94 r51.18
  region: -265.79,-989.05 345.51,-989.05 372.85,-1058.94 420.51,-1107.17 475.51,-1033.94 475.51,-968.94 430.51,-913.94 373.98,-899.05 -265.79,-899.05
  region: 285.51,-1316.98 708.98,-1316.98 669.87,-1218.83 360.51,-1218.83 342.85,-1188.94 255.9,-1289.27
  lines w10: -286.02,-899.05 -256.02,-989.05 ; -276.02,-899.05 -246.02,-989.05 ; -269.49,-898.94 -239.49,-988.94 ; -266.02,-989.05 -296.02,-899.05 363.98,-899.05 cw(c373.43,-1003.02) 444.45,-1079.55 323.74,-1218.83 669.87,-1218.83 ; -265.79,-989.05 -120.43,-989.05 ; -161.94,-1249.38 -331.21,-825.07 434.53,-825.07 ; -161.91,-1249.47 ccw(c-61.54,-1209.32) -51.75,-1316.98 708.98,-1316.98 537.87,-888.04 ; -120.43,-979.05 -6.67,-1308.94 ; -111.42,-979.39 1.54,-1306.98 ; -101.42,-979.39 11.54,-1306.98 ; -91.42,-979.39 21.54,-1306.98 ; -81.42,-979.39 31.54,-1306.98 ; -71.42,-979.39 41.54,-1306.98 ; -61.42,-979.39 51.54,-1306.98 ; -56.02,-989.05 455.51,-989.05 ; -51.42,-979.39 61.54,-1306.98 ; -41.42,-979.39 71.54,-1306.98 ; -36.42,-979.39 76.54,-1306.98 ; -28.46,-979.05 85.3,-1308.94 ; 220.51,-1223.94 429.37,-982.95 ; 220.51,-1208.94 429.37,-967.95 ; 225.51,-1238.94 434.37,-997.95 ; 225.51,-1228.94 434.37,-987.95 ; 225.51,-1193.94 434.37,-952.95 ; 227.66,-1246.46 434.37,-1007.95 ; 228.36,-1177.07 437.22,-936.08 ; 230.51,-1253.94 439.37,-1012.95 ; 235.51,-1258.94 444.37,-1017.95 ; 240.51,-1263.94 449.37,-1022.95 ; 245.51,-1268.94 454.37,-1027.95 ; 250.51,-1283.94 459.37,-1042.95 ; 250.51,-1273.94 459.37,-1032.95 ; 255.9,-1289.27 469.37,-1042.95 ; 295.69,-1313.34 cw(c324.53,-1213) 253.51,-1136.47 346.62,-1029.05 ccw(c333.61,-1010.85) 332.59,-988.52 ; 359.51,-1180.29 ccw(c371.23,-1198.29) 375.37,-1219.36 ; 434.58,-825.07 cw(c443.89,-927.52) 539.41,-889.31
  lines w11.81: -6.67,-1308.94 85.3,-1308.94 ; 771.31,-1469.98 771.31,-682.57 ; 771.31,-1273.13 3133.51,-1273.13 ; 771.31,-1076.28 3133.51,-1076.28 ; 771.31,-879.43 3133.51,-879.43 ; 1558.71,-1469.98 1558.71,-879.43 ; -409.8,-1469.98 -409.8,-682.57 3133.51,-682.57 3133.51,-1469.98 -409.8,-1469.98
  text "Project: '.Board_Name'" at 3086.5,-809.19 h118.11
  text "Gerber:" at 1512.14,-1009.35 h118.11
  text "Layer:" at 3086.5,-1009.35 h118.11
  text "Ref: '.Board_Reference'" at 1512.14,-1206.2 h118.11
  text "Variant: '.VariantName'" at 3086.5,-1206.2 h118.11
  text "R" at -264.49,-1303.94 h60
  text "Rev: '.Board_PCB_Revision'" at 1514.39,-1403.05 h118.11
  text "Date: '.Board_Document_Date'" at 3086.5,-1403.05 h118.11
Board Dimensions:
  lines w10: -720.79,0 1249.21,0 ; -720.79,3818.9 1249.21,3818.9 ; -670.79,1841.95 -670.79,0 ; -670.79,1976.95 -670.79,3818.9 ; -390.79,2487.4 199.21,2487.4 ; -390.79,3587.4 199.21,3587.4 ; -340.79,2969.9 -340.79,2487.4 ; -340.79,3104.9 -340.79,3587.4 ; 0,1959.45 0,4468.9 ; 249.21,-371.1 249.21,37.4 ; 249.21,3737.4 249.21,4288.9 ; 349.21,-151.1 349.21,37.4 ; 1058.99,-321.1 249.21,-321.1 ; 1058.99,4238.9 249.21,4238.9 ; 1061.26,-101.1 349.21,-101.1 ; 1063.53,4418.9 0,4418.9 ; 1534.89,4418.9 2598.43,4418.9 ; 1537.17,-101.1 2249.21,-101.1 ; 1539.44,-321.1 2349.21,-321.1 ; 1539.44,4238.9 2349.21,4238.9 ; 2249.21,-151.1 2249.21,37.4 ; 2349.21,-371.1 2349.21,37.4 ; 2349.21,3737.4 2349.21,4288.9 ; 2598.43,1959.45 2598.43,4468.9 ; -670.79,0 -695.79,100 -645.79,100 -670.79,0 ; -670.79,3818.9 -695.79,3718.9 -645.79,3718.9 -670.79,3818.9 ; -340.79,2487.4 -365.79,2587.4 -315.79,2587.4 -340.79,2487.4 ; -340.79,3587.4 -315.79,3487.4 -365.79,3487.4 -340.79,3587.4 ; 0,4418.9 100,4393.9 100,4443.9 0,4418.9 ; 249.21,-321.1 349.21,-346.1 349.21,-296.1 249.21,-321.1 ; 249.21,4238.9 349.21,4263.9 349.21,4213.9 249.21,4238.9 ; 349.21,-101.1 449.21,-76.1 449.21,-126.1 349.21,-101.1 ; 2249.21,-101.1 2149.21,-76.1 2149.21,-126.1 2249.21,-101.1 ; 2349.21,-321.1 2249.21,-346.1 2249.21,-296.1 2349.21,-321.1 ; 2349.21,4238.9 2249.21,4263.9 2249.21,4213.9 2349.21,4238.9 ; 2598.43,4418.9 2498.43,4443.9 2498.43,4393.9 2598.43,4418.9
  text "66.000mm" at 1093.53,4381.4 h50
  text "53.340mm" at 1088.99,4201.4 h50
  text "27.940mm" at -548.74,2999.9 h50
  text "97.000mm" at -877.61,1871.95 h50
  text "48.260mm" at 1091.26,-138.6 h50
  text "53.340mm" at 1088.99,-358.6 h50
  text "Board Dimensions" at -73,-1018.77 h118.11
